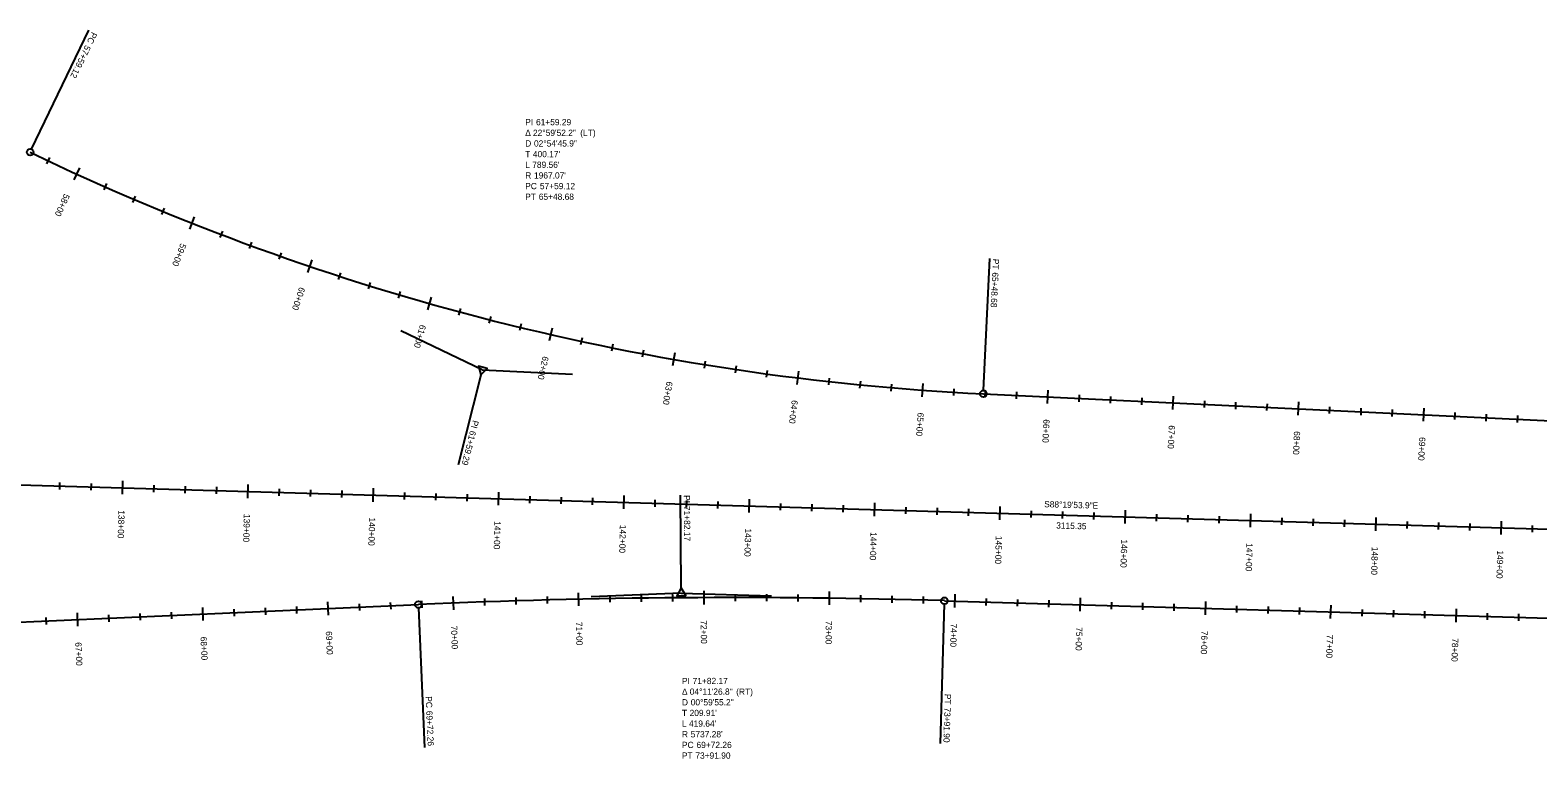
# Model space of a CAD drawing. Extents: x 2300830 to 2307917, y 756066 to 766359.
# Drawn here: x 2305519 to 2306721, y 760659 to 761240 of the extents above; entities that cross this region are included whole.
import ezdxf

# ---------------------------------------------------------------- set-up
doc = ezdxf.new("R2010")
doc.units = 0
for name, color, linetype in [('Default', 7, 'Continuous'), ('Draft_Bearing Label', 7, 'Continuous'), ('Draft_Curve Data Label', 7, 'Continuous'), ('Draft_Station Cardinal Lines', 7, 'Continuous'), ('Draft_Station Cardinal Points', 7, 'Continuous'), ('Draft_Station Labels Major', 7, 'Continuous'), ('Draft_Station Ticks Major', 7, 'Continuous'), ('Draft_Station Ticks Minor', 7, 'Continuous'), ('Geom_Baseline', 7, 'Continuous')]:
    doc.layers.add(name, color=color, linetype=linetype)

msp = doc.modelspace()

# ---------------------------------------------------------------- linework, layer by layer
at = {"layer": 'Default'}
for p, q in [((2306279.1, 760949.8), (2307581, 760887.9)), ((2304792.6, 760898.1), (2307906.7, 760807.4)), ((2306248, 760784.7), (2307314.7, 760753.7)), ((2304213, 760710.4), (2305828.5, 760781.6))]:
    msp.add_line(p, q, dxfattribs=at)
for centre, radius, start, end in [((2306372.5, 762914.6), 1967.1, 244.2817, 267.2795), ((2306081, 755049.9), 5737.3, 88.33163, 92.52241)]:
    msp.add_arc(centre, radius, start, end, dxfattribs=at)
at = {"layer": 'Draft_Station Cardinal Lines'}
for p, q in [((2305520, 761144.8), (2305565.7, 761239.7)), ((2306279.2, 760952.5), (2306284.2, 761057.7)), ((2305879.4, 760968.8), (2305814.5, 761000)), ((2305878.4, 760964.7), (2305860.2, 760893.2)), ((2305879.4, 760968.8), (2305951.3, 760965.4)), ((2306038.2, 760795), (2306037.6, 760868.8)), ((2306038.2, 760790.8), (2305966.3, 760787.7)), ((2306038.2, 760790.8), (2306110.2, 760788.7)), ((2306247.9, 760782.1), (2306244.7, 760670.8)), ((2305828.6, 760778.9), (2305833.5, 760667.7))]:
    msp.add_line(p, q, dxfattribs=at)
for points in [[(2305878.4, 760964.8), (2305883.4, 760969.9), (2305876.4, 760971.7)], [(2306038.2, 760795), (2306034.6, 760788.7), (2306041.8, 760788.8)]]:
    msp.add_lwpolyline(points, close=True, dxfattribs=at)
at = {"layer": 'Draft_Station Cardinal Points'}
for p, q in [((2305565.7, 761239.7), (2305565.7, 761239.7)), ((2305518.9, 761142.4), (2305518.9, 761142.4)), ((2306284.2, 761057.7), (2306284.2, 761057.7)), ((2305879.4, 760968.8), (2305879.4, 760968.8)), ((2306279.1, 760949.8), (2306279.1, 760949.8)), ((2305860.2, 760893.2), (2305860.2, 760893.2)), ((2306037.6, 760868.8), (2306037.6, 760868.8)), ((2306038.2, 760790.8), (2306038.2, 760790.8)), ((2306248, 760784.7), (2306248, 760784.7)), ((2305828.5, 760781.6), (2305828.5, 760781.6)), ((2305833.5, 760667.7), (2305833.5, 760667.7)), ((2306244.7, 760670.8), (2306244.7, 760670.8))]:
    msp.add_line(p, q, dxfattribs=at)
for centre in [(2305518.9, 761142.4), (2306279.1, 760949.8), (2305828.5, 760781.6), (2306248, 760784.7)]:
    msp.add_circle(centre, 2.67, dxfattribs=at)
at = {"layer": 'Draft_Station Ticks Major'}
for p, q in [((2305558.1, 761129.9), (2305553.7, 761120.3)), ((2305649.8, 761090.9), (2305645.9, 761081)), ((2305743.4, 761056.5), (2305740, 761046.4)), ((2305838.7, 761026.9), (2305835.8, 761016.7)), ((2305935.3, 761002.2), (2305932.9, 760991.9)), ((2306033, 760982.5), (2306031.2, 760972)), ((2306131.7, 760967.7), (2306130.4, 760957.2)), ((2306230.9, 760958), (2306230.1, 760947.4)), ((2306330.6, 760952.7), (2306330.1, 760942.1)), ((2306430.5, 760947.9), (2306430, 760937.3)), ((2306530.4, 760943.2), (2306529.9, 760932.6)), ((2306630.3, 760938.4), (2306629.8, 760927.8)), ((2305592.5, 760880.2), (2305592.2, 760869.6)), ((2305692.5, 760877.3), (2305692.1, 760866.6)), ((2305792.4, 760874.4), (2305792.1, 760863.7)), ((2305892.4, 760871.4), (2305892.1, 760860.8)), ((2305992.3, 760868.5), (2305992, 760857.9)), ((2306092.3, 760865.6), (2306092, 760855)), ((2306192.2, 760862.7), (2306191.9, 760852.1)), ((2306292.2, 760859.8), (2306291.9, 760849.2)), ((2306392.2, 760856.9), (2306391.9, 760846.3)), ((2306492.1, 760854), (2306491.8, 760843.4)), ((2306592.1, 760851.1), (2306591.8, 760840.4)), ((2306692, 760848.2), (2306691.7, 760837.5)), ((2305756.1, 760783.8), (2305756.5, 760773.2)), ((2305856, 760788.1), (2305856.4, 760777.5)), ((2305956, 760791.1), (2305956.3, 760780.5)), ((2306056.1, 760792.5), (2306056.2, 760781.8)), ((2306156.2, 760792), (2306156.1, 760781.4)), ((2306256.3, 760789.8), (2306256, 760779.2)), ((2306356.2, 760786.9), (2306355.9, 760776.3)), ((2306456.2, 760784), (2306455.9, 760773.4)), ((2305556.3, 760775), (2305556.7, 760764.3)), ((2305656.2, 760779.4), (2305656.6, 760768.8)), ((2306556.2, 760781.1), (2306555.8, 760770.5)), ((2306656.1, 760778.2), (2306655.8, 760767.6))]:
    msp.add_line(p, q, dxfattribs=at)
at = {"layer": 'Draft_Station Ticks Minor'}
for p, q in [((2305534.4, 761138.1), (2305532, 761133.1)), ((2305579.8, 761117.4), (2305577.6, 761112.3)), ((2305602.7, 761107.4), (2305600.5, 761102.4)), ((2305625.7, 761097.8), (2305623.6, 761092.7)), ((2305672.2, 761079.4), (2305670.2, 761074.3)), ((2305695.5, 761070.7), (2305693.6, 761065.5)), ((2305719, 761062.2), (2305717.2, 761057)), ((2305766.3, 761046.2), (2305764.6, 761040.9)), ((2305790.1, 761038.6), (2305788.5, 761033.4)), ((2305814, 761031.4), (2305812.4, 761026.1)), ((2305862, 761017.8), (2305860.6, 761012.5)), ((2305886.2, 761011.5), (2305884.8, 761006.1)), ((2305910.4, 761005.4), (2305909.1, 761000.1)), ((2305959.1, 760994.3), (2305957.9, 760988.9)), ((2305983.5, 760989.2), (2305982.4, 760983.8)), ((2306008, 760984.4), (2306007, 760979)), ((2306057.2, 760975.8), (2306056.3, 760970.3)), ((2306081.9, 760971.9), (2306081.1, 760966.5)), ((2306106.6, 760968.4), (2306105.8, 760962.9)), ((2306156.1, 760962.3), (2306155.5, 760956.8)), ((2306181, 760959.7), (2306180.4, 760954.2)), ((2306205.8, 760957.4), (2306205.4, 760951.9)), ((2306255.6, 760953.8), (2306255.3, 760948.3)), ((2306280.6, 760952.5), (2306280.3, 760947)), ((2306305.5, 760951.3), (2306305.3, 760945.8)), ((2306355.5, 760948.9), (2306355.2, 760943.4)), ((2306380.4, 760947.7), (2306380.2, 760942.2)), ((2306405.4, 760946.5), (2306405.2, 760941)), ((2306455.4, 760944.2), (2306455.1, 760938.7)), ((2306480.3, 760943), (2306480.1, 760937.5)), ((2306505.3, 760941.8), (2306505, 760936.3)), ((2306555.2, 760939.4), (2306555, 760933.9)), ((2306580.2, 760938.2), (2306580, 760932.7)), ((2306605.2, 760937.1), (2306604.9, 760931.5)), ((2306655.1, 760934.7), (2306654.9, 760929.2)), ((2306680.1, 760933.5), (2306679.8, 760928)), ((2306705.1, 760932.3), (2306704.8, 760926.8)), ((2305542.4, 760879.1), (2305542.3, 760873.5)), ((2305567.4, 760878.3), (2305567.3, 760872.8)), ((2305617.4, 760876.9), (2305617.3, 760871.4)), ((2305642.4, 760876.1), (2305642.2, 760870.6)), ((2305667.4, 760875.4), (2305667.2, 760869.9)), ((2305717.4, 760874), (2305717.2, 760868.4)), ((2305742.4, 760873.2), (2305742.2, 760867.7)), ((2305767.4, 760872.5), (2305767.2, 760867)), ((2305817.3, 760871), (2305817.2, 760865.5)), ((2305842.3, 760870.3), (2305842.2, 760864.8)), ((2305867.3, 760869.6), (2305867.1, 760864.1)), ((2305917.3, 760868.1), (2305917.1, 760862.6)), ((2305942.3, 760867.4), (2305942.1, 760861.9)), ((2305967.3, 760866.7), (2305967.1, 760861.2)), ((2306017.2, 760865.2), (2306017.1, 760859.7)), ((2306042.2, 760864.5), (2306042.1, 760859)), ((2306067.2, 760863.8), (2306067.1, 760858.3)), ((2306117.2, 760862.3), (2306117, 760856.8)), ((2306142.2, 760861.6), (2306142, 760856.1)), ((2306167.2, 760860.9), (2306167, 760855.3)), ((2306217.2, 760859.4), (2306217, 760853.9)), ((2306242.2, 760858.7), (2306242, 760853.2)), ((2306267.1, 760857.9), (2306267, 760852.4)), ((2306317.1, 760856.5), (2306317, 760851)), ((2306342.1, 760855.8), (2306341.9, 760850.2)), ((2306367.1, 760855), (2306366.9, 760849.5)), ((2306417.1, 760853.6), (2306416.9, 760848.1)), ((2306442.1, 760852.9), (2306441.9, 760847.3)), ((2306467.1, 760852.1), (2306466.9, 760846.6)), ((2306517, 760850.7), (2306516.9, 760845.1)), ((2306542, 760849.9), (2306541.9, 760844.4)), ((2306567, 760849.2), (2306566.9, 760843.7)), ((2306617, 760847.8), (2306616.8, 760842.2)), ((2306642, 760847), (2306641.8, 760841.5)), ((2306667, 760846.3), (2306666.8, 760840.8)), ((2306716.9, 760844.8), (2306716.8, 760839.3)), ((2305781.2, 760782.3), (2305781.4, 760776.8)), ((2305806.1, 760783.4), (2305806.4, 760777.9)), ((2305831.1, 760784.5), (2305831.3, 760779)), ((2305881.1, 760786.4), (2305881.3, 760780.9)), ((2305906.1, 760787.3), (2305906.3, 760781.7)), ((2305931.1, 760788), (2305931.2, 760782.4)), ((2305981.1, 760789.1), (2305981.2, 760783.5)), ((2306006.1, 760789.4), (2306006.2, 760783.9)), ((2306031.1, 760789.7), (2306031.2, 760784.2)), ((2306081.1, 760789.9), (2306081.1, 760784.4)), ((2306106.2, 760789.9), (2306106.1, 760784.3)), ((2306131.2, 760789.7), (2306131.1, 760784.2)), ((2306181.2, 760789.1), (2306181.1, 760783.5)), ((2306206.2, 760788.6), (2306206.1, 760783)), ((2306231.2, 760788), (2306231.1, 760782.4)), ((2306281.2, 760786.5), (2306281, 760781)), ((2306306.2, 760785.8), (2306306, 760780.3)), ((2306331.2, 760785.1), (2306331, 760779.6)), ((2306381.2, 760783.6), (2306381, 760778.1)), ((2306406.1, 760782.9), (2306406, 760777.4)), ((2306431.1, 760782.2), (2306431, 760776.6)), ((2305531.4, 760771.3), (2305531.6, 760765.8)), ((2305581.3, 760773.5), (2305581.6, 760768)), ((2305606.3, 760774.6), (2305606.6, 760769.1)), ((2305631.3, 760775.7), (2305631.5, 760770.2)), ((2305681.3, 760777.9), (2305681.5, 760772.4)), ((2305706.2, 760779), (2305706.5, 760773.5)), ((2305731.2, 760780.1), (2305731.4, 760774.6)), ((2306481.1, 760780.7), (2306480.9, 760775.2)), ((2306506.1, 760780), (2306505.9, 760774.5)), ((2306531.1, 760779.2), (2306530.9, 760773.7)), ((2306581.1, 760777.8), (2306580.9, 760772.3)), ((2306606.1, 760777.1), (2306605.9, 760771.5)), ((2306631, 760776.3), (2306630.9, 760770.8)), ((2306681, 760774.9), (2306680.9, 760769.4)), ((2306706, 760774.2), (2306705.9, 760768.6))]:
    msp.add_line(p, q, dxfattribs=at)
at = {"layer": 'Geom_Baseline'}
for p, q in [((2306279.1, 760949.8), (2307581, 760887.9)), ((2304792.6, 760898.1), (2307906.7, 760807.4)), ((2306248, 760784.7), (2307314.7, 760753.7)), ((2304213, 760710.4), (2305828.5, 760781.6))]:
    msp.add_line(p, q, dxfattribs=at)
for centre, radius, start, end in [((2306372.5, 762914.6), 1967.1, 244.2817, 267.2795), ((2306081, 755049.9), 5737.3, 88.33163, 92.52241)]:
    msp.add_arc(centre, radius, start, end, dxfattribs=at)

# ---------------------------------------------------------------- texts
at = {"layer": 'Draft_Bearing Label'}
for s, p in [('S88°19\'53.9"E', (2306327.5, 760859.3)), ('3115.35', (2306337.1, 760842.3))]:
    msp.add_text(s, height=5, rotation=358.3316, dxfattribs=at).set_placement(p)
at = {"layer": 'Draft_Curve Data Label'}
for s, p in [('PI ', (2305913.7, 761163.9)), ('61+59.29', (2305922.3, 761163.9)), ('Δ ', (2305913.7, 761155.4)), ('22°59\'52.2"', (2305919.9, 761155.4)), (' (LT)', (2305955.7, 761155.4)), ('T ', (2305913.7, 761138.4)), ('D ', (2305913.7, 761146.9)), ("400.17'", (2305919.8, 761138.4)), ('02°54\'45.9"', (2305920.7, 761146.9)), ('L ', (2305913.7, 761129.9)), ("789.56'", (2305919.3, 761129.9)), ('R ', (2305913.7, 761121.4)), ("1967.07'", (2305920.7, 761121.4)), ('PC ', (2305913.7, 761112.9)), ('PT ', (2305913.7, 761104.4)), ('65+48.68', (2305924.5, 761104.4)), ('57+59.12', (2305925.4, 761112.9)), ('PI ', (2306038.7, 760718.2)), ('71+82.17', (2306047.2, 760718.2)), ('Δ ', (2306038.7, 760709.7)), ('04°11\'26.8"', (2306044.9, 760709.7)), (' (RT)', (2306080.1, 760709.7)), ('T ', (2306038.7, 760692.7)), ('D ', (2306038.7, 760701.2)), ("209.91'", (2306044.8, 760692.7)), ('00°59\'55.2"', (2306045.7, 760701.2)), ('L ', (2306038.7, 760684.2)), ("419.64'", (2306044.3, 760684.2)), ('R ', (2306038.7, 760675.7)), ("5737.28'", (2306045.7, 760675.7)), ('PC ', (2306038.7, 760667.2)), ('PT ', (2306038.7, 760658.7)), ('73+91.90', (2306049.4, 760658.7)), ('69+72.26', (2306050.3, 760667.2))]:
    msp.add_text(s, height=5, dxfattribs=at).set_placement(p)
at = {"layer": 'Draft_Station Cardinal Points'}
for s, rotation, p in [('57+59.12', 244.2817, (2305562.9, 761228.2)), ('PC', 244.2817, (2305568, 761238.7)), ('65+48.68', 267.2795, (2306286.2, 761046.7)), ('PT', 267.2795, (2306286.7, 761057.5)), ('PI ', 255.7806, (2305871.9, 760929)), ('61+59.29', 255.7806, (2305869.8, 760920.7)), ('PI ', 270.427, (2306040.1, 760868.9)), ('71+82.17', 270.427, (2306040.2, 760860.3)), ('PT', 268.3316, (2306248.3, 760710.5)), ('PC', 272.5224, (2305834.2, 760708.4)), ('73+91.90', 268.3316, (2306248, 760699.7)), ('69+72.26', 272.5224, (2305834.7, 760696.8))]:
    msp.add_text(s, height=5, rotation=rotation, dxfattribs=at).set_placement(p)
at = {"layer": 'Draft_Station Labels Major'}
for s, rotation, p in [('58+00', 245.4724, (2305546.1, 761109.7)), ('59+00', 248.3851, (2305638.9, 761070.1)), ('60+00', 251.2979, (2305733.6, 761035.2)), ('61+00', 254.2106, (2305829.9, 761005.2)), ('62+00', 257.1234, (2305927.7, 760980)), ('63+00', 260.0361, (2306026.5, 760959.9)), ('64+00', 262.9489, (2306126.3, 760944.9)), ('65+00', 265.8616, (2306226.7, 760934.9)), ('66+00', 267.2795, (2306327, 760929.5)), ('67+00', 267.2795, (2306426.9, 760924.7)), ('68+00', 267.2795, (2306526.8, 760920)), ('69+00', 267.2795, (2306626.7, 760915.3)), ('138+00', 268.3316, (2305589.3, 760856.9)), ('139+00', 268.3316, (2305689.3, 760854)), ('140+00', 268.3316, (2305789.2, 760851.1)), ('141+00', 268.3316, (2305889.2, 760848.2)), ('142+00', 268.3316, (2305989.2, 760845.3)), ('143+00', 268.3316, (2306089.1, 760842.4)), ('144+00', 268.3316, (2306189.1, 760839.5)), ('145+00', 268.3316, (2306289, 760836.5)), ('146+00', 268.3316, (2306389, 760833.6)), ('147+00', 268.3316, (2306488.9, 760830.7)), ('148+00', 268.3316, (2306588.9, 760827.8)), ('149+00', 268.3316, (2306688.9, 760824.9)), ('69+00', 272.5224, (2305754.6, 760760.3)), ('70+00', 272.2453, (2305854.4, 760764.7)), ('71+00', 271.2467, (2305954.1, 760767.8)), ('72+00', 270.248, (2306053.7, 760769.1)), ('73+00', 269.2494, (2306153.4, 760768.7)), ('74+00', 268.3316, (2306253.1, 760766.6)), ('75+00', 268.3316, (2306353.1, 760763.7)), ('76+00', 268.3316, (2306453, 760760.8)), ('67+00', 272.5224, (2305554.8, 760751.5)), ('68+00', 272.5224, (2305654.7, 760755.9)), ('77+00', 268.3316, (2306553, 760757.8)), ('78+00', 268.3316, (2306652.9, 760754.9))]:
    msp.add_text(s, height=5, rotation=rotation, dxfattribs=at).set_placement(p)

doc.saveas('drawing.dxf')
